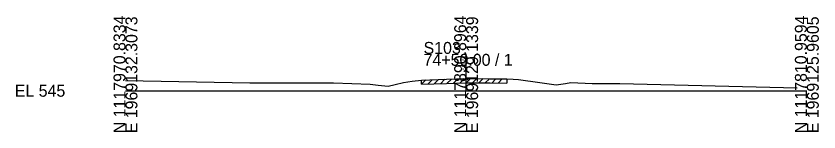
# Model space of a CAD drawing. Extents: x -26 to 163, y -10 to 45020.
# Drawn here: x -25.7 to 162.8, y 33490.3 to 33517.6 of the extents above; entities that cross this region are included whole.
import ezdxf

# ---------------------------------------------------------------- set-up
doc = ezdxf.new("R2010")
doc.units = 0
for name, color, linetype in [('RD_GPK_XS_Cell', 7, 'Continuous'), ('RD_XS_ExGround', 7, 'Continuous'), ('RD_XS_ExPaveRet', 7, 'Continuous'), ('RD_XS_TX_Elev_EX', 7, 'Continuous')]:
    doc.layers.add(name, color=color, linetype=linetype)

msp = doc.modelspace()

# ---------------------------------------------------------------- linework, layer by layer
at = {"layer": 'RD_GPK_XS_Cell'}
for p, q in [((80, 33500), (80, 33508.68)), ((0, 33500), (80, 33500)), ((80, 33500), (160, 33500))]:
    msp.add_line(p, q, dxfattribs=at)
at = {"layer": 'RD_XS_ExGround'}
for p, q in [((0, 33502.4), (29.19, 33501.9)), ((65.3, 33501.97), (67.35, 33502.24)), ((67.35, 33502.24), (69.5, 33502.52)), ((69.5, 33502.52), (75.35, 33502.71)), ((75.35, 33502.71), (80, 33502.86)), ((80, 33502.86), (80.93, 33502.89)), ((80.93, 33502.89), (85.61, 33502.83)), ((85.61, 33502.83), (89.55, 33502.79)), ((89.55, 33502.79), (91.07, 33502.71)), ((91.07, 33502.71), (92.31, 33502.65)), ((92.31, 33502.65), (97.3, 33501.97)), ((29.19, 33501.9), (48.81, 33501.84)), ((48.81, 33501.84), (57.48, 33501.53)), ((57.48, 33501.53), (59.34, 33501.28)), ((59.34, 33501.28), (61.69, 33501.05)), ((61.69, 33501.05), (63.31, 33501.49)), ((63.31, 33501.49), (65.3, 33501.97)), ((97.3, 33501.97), (101.14, 33501.43)), ((101.14, 33501.43), (103.3, 33501.71)), ((103.3, 33501.71), (104.61, 33501.94)), ((104.61, 33501.94), (109.6, 33501.74)), ((109.6, 33501.74), (116.08, 33501.72)), ((116.08, 33501.72), (157.76, 33500.67))]:
    msp.add_line(p, q, dxfattribs=at)
at = {"layer": 'RD_XS_ExPaveRet'}
for p, q in [((69.5, 33501.52), (70.53, 33502.56)), ((69.5, 33501.52), (69.5, 33502.52)), ((71, 33501.57), (72.03, 33502.61)), ((72.5, 33501.62), (73.53, 33502.65)), ((74, 33501.67), (75.03, 33502.7)), ((75.5, 33501.72), (76.53, 33502.75)), ((77, 33501.76), (78.03, 33502.8)), ((78.5, 33501.81), (79.53, 33502.85)), ((80, 33501.86), (81.02, 33502.89)), ((81.5, 33501.88), (82.48, 33502.87)), ((83, 33501.86), (83.98, 33502.85)), ((84.5, 33501.84), (85.48, 33502.83)), ((86, 33501.82), (86.99, 33502.82)), ((87.5, 33501.81), (88.49, 33502.8)), ((89.55, 33502.79), (89.55, 33501.79)), ((69.5, 33501.52), (75.35, 33501.71)), ((75.35, 33501.71), (80, 33501.86)), ((80, 33501.86), (80.93, 33501.89)), ((80.93, 33501.89), (85.61, 33501.83)), ((85.61, 33501.83), (89.55, 33501.79))]:
    msp.add_line(p, q, dxfattribs=at)

# ---------------------------------------------------------------- texts
at = {"layer": 'RD_GPK_XS_Cell'}
for s, p in [('N 1117970.8334', (0, 33490)), ('N 1117890.8964', (80, 33490)), ('N 1117810.9594', (160, 33490)), ('E 1969125.9605', (162.8, 33490)), ('E 1969132.3073', (2.8, 33490)), ('E 1969129.1339', (82.8, 33490))]:
    msp.add_text(s, height=2.8, rotation=90, dxfattribs=at).set_placement(p)
for s, p in [('S103', (70, 33508.68)), ('74+50.00 / 1', (70, 33505.88)), ('EL 545', (-26, 33498.6))]:
    msp.add_text(s, height=2.8, dxfattribs=at).set_placement(p)
at = {"layer": 'RD_XS_TX_Elev_EX'}
msp.add_text('547.86', height=0.8, rotation=90, dxfattribs=at).set_placement((79.9, 33504.86))

doc.saveas('drawing.dxf')
